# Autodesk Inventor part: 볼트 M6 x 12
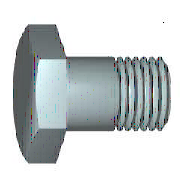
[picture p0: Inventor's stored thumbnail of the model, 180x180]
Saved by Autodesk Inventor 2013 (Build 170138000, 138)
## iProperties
IsCustomPart: 0
Created: 2012-02
Part Number: 볼트 M6 x 12
Material: 스테인리스강
Description: 6각 머리 나사. 제품 등급 C
Document SubType Name: Modeling
Standard: ISO 4018
Designer: mduedu
Standard Revision: Third edition 1999-08-15
Standards Organization: ISO
Language: ko-KR
Size Designation: M6 x 12
Categories: <MemberInstance><Categories><Category DisplayName="조임쇠" InternalName="e4da775c-781d-43d5-af7c-5136215cf5a6" Mnemonic="FSTN"><Category DisplayName="볼트" InternalN
Density: 8.08 g/cm^3
Author: mduedu
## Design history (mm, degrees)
node "WorkPlane1"
node "WorkPoint1"
node "MSC_A1"
node "MSC_PF1"
node "MSC_PT1"
body "Solid1"
node "스케치1"
sketch "스케치2"
  geometry: L1 (-5, 2.887)-(-5, -2.887); L2 (0, 5.773)-(-5, 2.887); L3 (5, 2.887)-(0, 5.773); L4 (5, -2.887)-(5, 2.887); L5 (0, -5.773)-(5, -2.887); L6 (-5, -2.887)-(0, -5.773); C1 r 5 at (0, 0); 1 further point
  constraints: 12 end point, 6 tangent, 2 parallel, 2 vertical, 1 centre point
  dimensions: "d1" = 10 diameter of C1 (= ParS); "d29" = 0 distance of point (0, 0) C1.centre; "d30" = 0 distance of C1.centre point (0, 0)
extrude "돌출1" new body sketch "스케치2" distance "d6" = 4 (= ParK); taper "d7" = 0 deg
revolve "회전1" stored, may be unused: angle "d14" = 360 deg
revolve "회전2" stored, may be unused: angle "d21" = 360 deg
chamfer "모따기1" distance "d22" = 0.5 (= 0.5 x PTC); stored, may be unused: second distance "d23" = 0.5 (= 0.5 x PTC), angle "d39" = 45 deg
fillet "모깎기1" dims "d24" = 0.25 (= r)
feature "스레드1" dims "d32" = 0, "b" = 10 (= NLG - 2 x PTC)
sketch "스케치3"
  geometry: L1 (5, 4)-(5.873, 4); L2 (5.873, 3.496)-(5, 4); L3 (5.873, 4)-(5.873, 3.496); L4 (0, -0.8)-(0, 4.8) reference; L5 (5.773, 0)-(5.773, 4) reference
  constraints: 6 end point, 1 horizontal, 1 vertical
  dimensions: "d25" = 0.1 distance between parallel lines of L5 L3; "d26" = 0 distance from line of L5.end L1; "d27" = 60 deg angle of L3 L2; "d28" = 5 distance from line of L4 L1.start (= 0.5 x ParS)
sketch "스케치4"
  geometry: L1 (0, -12)-(0, 0); L2 (-3, -12)-(0, -12); L3 (-3, 0)-(-3, -12); L4 (0, 0)-(-3, 0); L5 (0, -12)-(0, 0); L6 (-3.6, 0)-(0.6, 0) reference; L7 (0, -14.4)-(0, 2.4) reference
  constraints: 10 end point, 2 horizontal, 2 vertical
  dimensions: "d18" = 3 distance of L1.start L2.start (= 0.5 x NND); "d20" = 12 distance of L3.start L2.start (= NLG); "d33" = 0 distance between parallel lines of L7 L1; "d34" = 0 distance between parallel lines of L6 L4
other parameters: "NND" = 6 [user parameter; used in 2 equation terms], "NLG" = 12 [user parameter; used in 2 equation terms], "PTC" = 1 [user parameter; used in 3 equation terms], "ParK" = 4 [user parameter; used in 1 equation term], "ParS" = 10 [user parameter; used in 3 equation terms], "msp_es" = 5.77367 (= 0.577367 x ParS) [user parameter], "r" = 0.25 [user parameter; used in 1 equation term], "d2" = 15 (derived), "d4" = 17.32102 (derived), "d8" = 15 (derived), "d10" = 0 (derived), "d12" = 30 deg (derived), "d15" = 0 (derived), "d37" = 0, "d38" = 0, "d40" = 0, "d41" = 0, "d42" = 0, "THREADDIA" = 6 (= NND) [user parameter]
